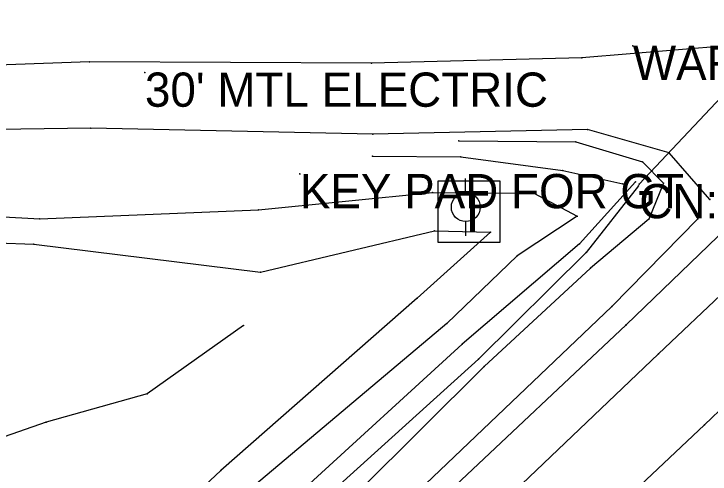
# Model space of a CAD drawing. Extents: x 1419505 to 1434054, y 1956910 to 1968644.
# Drawn here: x 1432529.3 to 1432631, y 1967186.4 to 1967253.6 of the extents above; entities that cross this region are included whole.
import ezdxf

# ---------------------------------------------------------------- set-up
doc = ezdxf.new("R2010")
doc.units = 0
for name, color, linetype in [('S_BREAKLINE', 7, 'Continuous'), ('S_DITCHLINE', 7, 'Continuous'), ('S_DRG_PT_SYM', 7, 'Continuous'), ('S_EDGE_PAVEMENT', 7, 'Continuous'), ('S_GATE_ANNOT', 7, 'Continuous'), ('S_GRAVEL_ROAD', 7, 'Continuous'), ('S_GRD_PT_SYM', 7, 'Continuous'), ('S_MISC_STRUCTURES_ANNOT', 7, 'Continuous'), ('S_MSC_PT_SYM', 7, 'Continuous'), ('S_PAVEMENT_CROWN', 7, 'Continuous'), ('S_RDW_PT_SYM', 7, 'Continuous'), ('S_SHOULDER', 7, 'Continuous'), ('S_SIDE_DRAIN', 7, 'Continuous'), ('S_SIDE_DRAIN_ANNOT', 7, 'Continuous'), ('S_SURVEY_TEXT_ANNOT', 7, 'Continuous'), ('S_TELEPHONE_UTILITIES', 7, 'Continuous')]:
    doc.layers.add(name, color=color, linetype=linetype)

msp = doc.modelspace()

# ---------------------------------------------------------------- linework, layer by layer
at = {"layer": 'S_BREAKLINE'}
for p, q in [((1432594.3055, 1967235.0941), (1432611.3766, 1967234.9541)), ((1432611.3766, 1967234.9541), (1432621.0802, 1967232.0329)), ((1432621.0802, 1967232.0329), (1432624.1824, 1967228.9217)), ((1432624.1824, 1967228.9217), (1432622.0503, 1967223.6513)), ((1432565.0346, 1967224.9874), (1432590.4573, 1967227.5466)), ((1432590.4573, 1967227.5466), (1432605.2522, 1967227.4596)), ((1432605.2522, 1967227.4596), (1432611.5856, 1967224.0844)), ((1432489.0497, 1967226.2985), (1432533.0896, 1967223.6753)), ((1432533.0896, 1967223.6753), (1432565.0346, 1967224.9874)), ((1432611.5856, 1967224.0844), (1432602.8181, 1967218.263)), ((1432622.0503, 1967223.6513), (1432613.4947, 1967216.4619)), ((1432629.1668, 1967223.6783), (1432616.6269, 1967210.8735)), ((1432565.3046, 1967215.9048), (1432590.7483, 1967221.9152)), ((1432598.9288, 1967221.7462), (1432588.1901, 1967212.1096)), ((1432590.7483, 1967221.9152), (1432598.9288, 1967221.7462)), ((1432489.4507, 1967221.5802), (1432532.2115, 1967219.9741)), ((1432532.2115, 1967219.9741), (1432565.3046, 1967215.9048)), ((1432602.8181, 1967218.263), (1432592.5354, 1967208.3994)), ((1432613.4947, 1967216.4619), (1432597.9657, 1967202.1109)), ((1432588.1901, 1967212.1096), (1432559.5073, 1967186.919)), ((1432616.6269, 1967210.8735), (1432570.1649, 1967166.6427)), ((1432562.8275, 1967208.1103), (1432548.7766, 1967198.1167)), ((1432592.5354, 1967208.3994), (1432562.6185, 1967183.2037)), ((1432597.9657, 1967202.1109), (1432571.475, 1967175.7472)), ((1432548.7766, 1967198.1167), (1432534.0146, 1967193.9934)), ((1432534.0146, 1967193.9934), (1432520.4247, 1967189.2581)), ((1432559.5073, 1967186.919), (1432543.0472, 1967171.614))]:
    msp.add_line(p, q, dxfattribs=at)
at = {"layer": 'S_DITCHLINE'}
for p, q in [((1432581.6877, 1967232.8479), (1432594.5755, 1967232.7279)), ((1432594.5755, 1967232.7279), (1432609.4605, 1967230.7678)), ((1432609.4605, 1967230.7678), (1432618.2151, 1967228.7927)), ((1432620.0602, 1967229.1027), (1432611.9246, 1967220.0431)), ((1432620.5392, 1967228.5157), (1432612.8927, 1967218.749)), ((1432611.9246, 1967220.0431), (1432594.7625, 1967205.3892)), ((1432612.8927, 1967218.749), (1432597.1437, 1967203.177)), ((1432594.7625, 1967205.3892), (1432566.7357, 1967179.7665)), ((1432597.1437, 1967203.177), (1432569.0119, 1967177.7844))]:
    msp.add_line(p, q, dxfattribs=at)
at = {"layer": 'S_DRG_PT_SYM'}
msp.add_lwpolyline([(1432620.6352, 1967228.7737), (1432620.6352, 1967228.8237), (1432620.6352, 1967228.7737), (1432620.5852, 1967228.7737), (1432620.6352, 1967228.7737), (1432620.6352, 1967228.7237), (1432620.6352, 1967228.7737), (1432620.6852, 1967228.7737)], dxfattribs=at)
at = {"layer": 'S_EDGE_PAVEMENT'}
for p, q in [((1432647.846, 1967227.1466), (1432623.4514, 1967203.9651)), ((1432623.4514, 1967203.9651), (1432576.4614, 1967159.2652))]:
    msp.add_line(p, q, dxfattribs=at)
at = {"layer": 'S_GRAVEL_ROAD'}
for p, q in [((1432540.563, 1967236.9162), (1432499.9084, 1967236.4522)), ((1432581.7447, 1967236.0441), (1432540.563, 1967236.9162)), ((1432613.0747, 1967236.7212), (1432581.7447, 1967236.0441)), ((1432625.0105, 1967233.325), (1432613.0747, 1967236.7212)), ((1432630.9139, 1967226.5365), (1432625.0105, 1967233.325))]:
    msp.add_line(p, q, dxfattribs=at)
at = {"layer": 'S_GRD_PT_SYM'}
for points in [[(1432594.3055, 1967235.0941), (1432594.3055, 1967235.1441), (1432594.3055, 1967235.0941), (1432594.2555, 1967235.0941), (1432594.3055, 1967235.0941), (1432594.3055, 1967235.0441), (1432594.3055, 1967235.0941), (1432594.3555, 1967235.0941)], [(1432611.3766, 1967234.9541), (1432611.3766, 1967235.0041), (1432611.3766, 1967234.9541), (1432611.3266, 1967234.9541), (1432611.3766, 1967234.9541), (1432611.3766, 1967234.9041), (1432611.3766, 1967234.9541), (1432611.4266, 1967234.9541)], [(1432581.6877, 1967232.8479), (1432581.6877, 1967232.8979), (1432581.6877, 1967232.8479), (1432581.6377, 1967232.8479), (1432581.6877, 1967232.8479), (1432581.6877, 1967232.7979), (1432581.6877, 1967232.8479), (1432581.7377, 1967232.8479)], [(1432594.5755, 1967232.7279), (1432594.5755, 1967232.7779), (1432594.5755, 1967232.7279), (1432594.5255, 1967232.7279), (1432594.5755, 1967232.7279), (1432594.5755, 1967232.6779), (1432594.5755, 1967232.7279), (1432594.6255, 1967232.7279)], [(1432621.0802, 1967232.0329), (1432621.0802, 1967232.0829), (1432621.0802, 1967232.0329), (1432621.0302, 1967232.0329), (1432621.0802, 1967232.0329), (1432621.0802, 1967231.9829), (1432621.0802, 1967232.0329), (1432621.1302, 1967232.0329)], [(1432609.4605, 1967230.7678), (1432609.4605, 1967230.8178), (1432609.4605, 1967230.7678), (1432609.4105, 1967230.7678), (1432609.4605, 1967230.7678), (1432609.4605, 1967230.7178), (1432609.4605, 1967230.7678), (1432609.5105, 1967230.7678)], [(1432618.2151, 1967228.7927), (1432618.2151, 1967228.8427), (1432618.2151, 1967228.7927), (1432618.1651, 1967228.7927), (1432618.2151, 1967228.7927), (1432618.2151, 1967228.7427), (1432618.2151, 1967228.7927), (1432618.2651, 1967228.7927)], [(1432620.0602, 1967229.1027), (1432620.0602, 1967229.1527), (1432620.0602, 1967229.1027), (1432620.0102, 1967229.1027), (1432620.0602, 1967229.1027), (1432620.0602, 1967229.0527), (1432620.0602, 1967229.1027), (1432620.1102, 1967229.1027)], [(1432624.1824, 1967228.9217), (1432624.1824, 1967228.9717), (1432624.1824, 1967228.9217), (1432624.1324, 1967228.9217), (1432624.1824, 1967228.9217), (1432624.1824, 1967228.8717), (1432624.1824, 1967228.9217), (1432624.2324, 1967228.9217)], [(1432620.5392, 1967228.5157), (1432620.5392, 1967228.5657), (1432620.5392, 1967228.5157), (1432620.4892, 1967228.5157), (1432620.5392, 1967228.5157), (1432620.5392, 1967228.4657), (1432620.5392, 1967228.5157), (1432620.5892, 1967228.5157)], [(1432590.4573, 1967227.5466), (1432590.4573, 1967227.5966), (1432590.4573, 1967227.5466), (1432590.4073, 1967227.5466), (1432590.4573, 1967227.5466), (1432590.4573, 1967227.4966), (1432590.4573, 1967227.5466), (1432590.5073, 1967227.5466)], [(1432605.2522, 1967227.4596), (1432605.2522, 1967227.5096), (1432605.2522, 1967227.4596), (1432605.2022, 1967227.4596), (1432605.2522, 1967227.4596), (1432605.2522, 1967227.4096), (1432605.2522, 1967227.4596), (1432605.3022, 1967227.4596)], [(1432565.0346, 1967224.9874), (1432565.0346, 1967225.0374), (1432565.0346, 1967224.9874), (1432564.9846, 1967224.9874), (1432565.0346, 1967224.9874), (1432565.0346, 1967224.9374), (1432565.0346, 1967224.9874), (1432565.0846, 1967224.9874)], [(1432533.0896, 1967223.6753), (1432533.0896, 1967223.7253), (1432533.0896, 1967223.6753), (1432533.0396, 1967223.6753), (1432533.0896, 1967223.6753), (1432533.0896, 1967223.6253), (1432533.0896, 1967223.6753), (1432533.1396, 1967223.6753)], [(1432611.5856, 1967224.0844), (1432611.5856, 1967224.1344), (1432611.5856, 1967224.0844), (1432611.5356, 1967224.0844), (1432611.5856, 1967224.0844), (1432611.5856, 1967224.0344), (1432611.5856, 1967224.0844), (1432611.6356, 1967224.0844)], [(1432629.1668, 1967223.6783), (1432629.1668, 1967223.7283), (1432629.1668, 1967223.6783), (1432629.1168, 1967223.6783), (1432629.1668, 1967223.6783), (1432629.1668, 1967223.6283), (1432629.1668, 1967223.6783), (1432629.2168, 1967223.6783)], [(1432622.0503, 1967223.6513), (1432622.0503, 1967223.7013), (1432622.0503, 1967223.6513), (1432622.0003, 1967223.6513), (1432622.0503, 1967223.6513), (1432622.0503, 1967223.6013), (1432622.0503, 1967223.6513), (1432622.1003, 1967223.6513)], [(1432590.7483, 1967221.9152), (1432590.7483, 1967221.9652), (1432590.7483, 1967221.9152), (1432590.6983, 1967221.9152), (1432590.7483, 1967221.9152), (1432590.7483, 1967221.8652), (1432590.7483, 1967221.9152), (1432590.7983, 1967221.9152)], [(1432598.9288, 1967221.7462), (1432598.9288, 1967221.7962), (1432598.9288, 1967221.7462), (1432598.8788, 1967221.7462), (1432598.9288, 1967221.7462), (1432598.9288, 1967221.6962), (1432598.9288, 1967221.7462), (1432598.9788, 1967221.7462)], [(1432532.2115, 1967219.9741), (1432532.2115, 1967220.0241), (1432532.2115, 1967219.9741), (1432532.1615, 1967219.9741), (1432532.2115, 1967219.9741), (1432532.2115, 1967219.9241), (1432532.2115, 1967219.9741), (1432532.2615, 1967219.9741)], [(1432611.9246, 1967220.0431), (1432611.9246, 1967220.0931), (1432611.9246, 1967220.0431), (1432611.8746, 1967220.0431), (1432611.9246, 1967220.0431), (1432611.9246, 1967219.9931), (1432611.9246, 1967220.0431), (1432611.9746, 1967220.0431)], [(1432612.8927, 1967218.749), (1432612.8927, 1967218.799), (1432612.8927, 1967218.749), (1432612.8427, 1967218.749), (1432612.8927, 1967218.749), (1432612.8927, 1967218.699), (1432612.8927, 1967218.749), (1432612.9427, 1967218.749)], [(1432602.8181, 1967218.263), (1432602.8181, 1967218.313), (1432602.8181, 1967218.263), (1432602.7681, 1967218.263), (1432602.8181, 1967218.263), (1432602.8181, 1967218.213), (1432602.8181, 1967218.263), (1432602.8681, 1967218.263)], [(1432565.3046, 1967215.9048), (1432565.3046, 1967215.9548), (1432565.3046, 1967215.9048), (1432565.2546, 1967215.9048), (1432565.3046, 1967215.9048), (1432565.3046, 1967215.8548), (1432565.3046, 1967215.9048), (1432565.3546, 1967215.9048)], [(1432613.4947, 1967216.4619), (1432613.4947, 1967216.5119), (1432613.4947, 1967216.4619), (1432613.4447, 1967216.4619), (1432613.4947, 1967216.4619), (1432613.4947, 1967216.4119), (1432613.4947, 1967216.4619), (1432613.5447, 1967216.4619)], [(1432588.1901, 1967212.1096), (1432588.1901, 1967212.1596), (1432588.1901, 1967212.1096), (1432588.1401, 1967212.1096), (1432588.1901, 1967212.1096), (1432588.1901, 1967212.0596), (1432588.1901, 1967212.1096), (1432588.2401, 1967212.1096)], [(1432616.6269, 1967210.8735), (1432616.6269, 1967210.9235), (1432616.6269, 1967210.8735), (1432616.5769, 1967210.8735), (1432616.6269, 1967210.8735), (1432616.6269, 1967210.8235), (1432616.6269, 1967210.8735), (1432616.6769, 1967210.8735)], [(1432562.8275, 1967208.1103), (1432562.8275, 1967208.1603), (1432562.8275, 1967208.1103), (1432562.7775, 1967208.1103), (1432562.8275, 1967208.1103), (1432562.8275, 1967208.0603), (1432562.8275, 1967208.1103), (1432562.8775, 1967208.1103)], [(1432592.5354, 1967208.3994), (1432592.5354, 1967208.4494), (1432592.5354, 1967208.3994), (1432592.4854, 1967208.3994), (1432592.5354, 1967208.3994), (1432592.5354, 1967208.3494), (1432592.5354, 1967208.3994), (1432592.5854, 1967208.3994)], [(1432594.7625, 1967205.3892), (1432594.7625, 1967205.4392), (1432594.7625, 1967205.3892), (1432594.7125, 1967205.3892), (1432594.7625, 1967205.3892), (1432594.7625, 1967205.3392), (1432594.7625, 1967205.3892), (1432594.8125, 1967205.3892)], [(1432597.1437, 1967203.177), (1432597.1437, 1967203.227), (1432597.1437, 1967203.177), (1432597.0937, 1967203.177), (1432597.1437, 1967203.177), (1432597.1437, 1967203.127), (1432597.1437, 1967203.177), (1432597.1937, 1967203.177)], [(1432597.9657, 1967202.1109), (1432597.9657, 1967202.1609), (1432597.9657, 1967202.1109), (1432597.9157, 1967202.1109), (1432597.9657, 1967202.1109), (1432597.9657, 1967202.0609), (1432597.9657, 1967202.1109), (1432598.0157, 1967202.1109)], [(1432548.7766, 1967198.1167), (1432548.7766, 1967198.1667), (1432548.7766, 1967198.1167), (1432548.7266, 1967198.1167), (1432548.7766, 1967198.1167), (1432548.7766, 1967198.0667), (1432548.7766, 1967198.1167), (1432548.8266, 1967198.1167)], [(1432534.0146, 1967193.9934), (1432534.0146, 1967194.0434), (1432534.0146, 1967193.9934), (1432533.9646, 1967193.9934), (1432534.0146, 1967193.9934), (1432534.0146, 1967193.9434), (1432534.0146, 1967193.9934), (1432534.0646, 1967193.9934)], [(1432559.5073, 1967186.919), (1432559.5073, 1967186.969), (1432559.5073, 1967186.919), (1432559.4573, 1967186.919), (1432559.5073, 1967186.919), (1432559.5073, 1967186.869), (1432559.5073, 1967186.919), (1432559.5573, 1967186.919)]]:
    msp.add_lwpolyline(points, dxfattribs=at)
at = {"layer": 'S_MSC_PT_SYM'}
for points in [[(1432619.7001, 1967248.964), (1432619.7001, 1967249.014), (1432619.7001, 1967248.964), (1432619.6501, 1967248.964), (1432619.7001, 1967248.964), (1432619.7001, 1967248.914), (1432619.7001, 1967248.964), (1432619.7501, 1967248.964)], [(1432548.4425, 1967245.0607), (1432548.4425, 1967245.1107), (1432548.4425, 1967245.0607), (1432548.3925, 1967245.0607), (1432548.4425, 1967245.0607), (1432548.4425, 1967245.0107), (1432548.4425, 1967245.0607), (1432548.4925, 1967245.0607)], [(1432571.06, 1967230.2388), (1432571.06, 1967230.2888), (1432571.06, 1967230.2388), (1432571.01, 1967230.2388), (1432571.06, 1967230.2388), (1432571.06, 1967230.1888), (1432571.06, 1967230.2388), (1432571.11, 1967230.2388)]]:
    msp.add_lwpolyline(points, dxfattribs=at)
at = {"layer": 'S_PAVEMENT_CROWN'}
for p, q in [((1432639.8124, 1967249.491), (1432612.2587, 1967247.2059)), ((1432612.2587, 1967247.2059), (1432581.5267, 1967246.4168)), ((1432540.352, 1967246.6358), (1432499.3144, 1967245.0467)), ((1432581.5267, 1967246.4168), (1432540.352, 1967246.6358)), ((1432656.4325, 1967218.923), (1432630.1618, 1967193.5964)), ((1432630.1618, 1967193.5964), (1432584.6329, 1967150.7456))]:
    msp.add_line(p, q, dxfattribs=at)
at = {"layer": 'S_RDW_PT_SYM'}
for points in [[(1432612.2587, 1967247.2059), (1432612.2587, 1967247.2559), (1432612.2587, 1967247.2059), (1432612.2087, 1967247.2059), (1432612.2587, 1967247.2059), (1432612.2587, 1967247.1559), (1432612.2587, 1967247.2059), (1432612.3087, 1967247.2059)], [(1432540.352, 1967246.6358), (1432540.352, 1967246.6858), (1432540.352, 1967246.6358), (1432540.302, 1967246.6358), (1432540.352, 1967246.6358), (1432540.352, 1967246.5858), (1432540.352, 1967246.6358), (1432540.402, 1967246.6358)], [(1432581.5267, 1967246.4168), (1432581.5267, 1967246.4668), (1432581.5267, 1967246.4168), (1432581.4767, 1967246.4168), (1432581.5267, 1967246.4168), (1432581.5267, 1967246.3668), (1432581.5267, 1967246.4168), (1432581.5767, 1967246.4168)], [(1432540.563, 1967236.9162), (1432540.563, 1967236.9662), (1432540.563, 1967236.9162), (1432540.513, 1967236.9162), (1432540.563, 1967236.9162), (1432540.563, 1967236.8662), (1432540.563, 1967236.9162), (1432540.613, 1967236.9162)], [(1432581.7447, 1967236.0441), (1432581.7447, 1967236.0941), (1432581.7447, 1967236.0441), (1432581.6947, 1967236.0441), (1432581.7447, 1967236.0441), (1432581.7447, 1967235.9941), (1432581.7447, 1967236.0441), (1432581.7947, 1967236.0441)], [(1432613.0747, 1967236.7212), (1432613.0747, 1967236.7712), (1432613.0747, 1967236.7212), (1432613.0247, 1967236.7212), (1432613.0747, 1967236.7212), (1432613.0747, 1967236.6712), (1432613.0747, 1967236.7212), (1432613.1247, 1967236.7212)], [(1432625.0105, 1967233.325), (1432625.0105, 1967233.375), (1432625.0105, 1967233.325), (1432624.9605, 1967233.325), (1432625.0105, 1967233.325), (1432625.0105, 1967233.275), (1432625.0105, 1967233.325), (1432625.0605, 1967233.325)], [(1432630.9139, 1967226.5365), (1432630.9139, 1967226.5865), (1432630.9139, 1967226.5365), (1432630.8639, 1967226.5365), (1432630.9139, 1967226.5365), (1432630.9139, 1967226.4865), (1432630.9139, 1967226.5365), (1432630.9639, 1967226.5365)], [(1432618.7421, 1967208.2263), (1432618.7421, 1967208.2763), (1432618.7421, 1967208.2263), (1432618.6921, 1967208.2263), (1432618.7421, 1967208.2263), (1432618.7421, 1967208.1763), (1432618.7421, 1967208.2263), (1432618.7921, 1967208.2263)], [(1432623.4514, 1967203.9651), (1432623.4514, 1967204.0151), (1432623.4514, 1967203.9651), (1432623.4014, 1967203.9651), (1432623.4514, 1967203.9651), (1432623.4514, 1967203.9151), (1432623.4514, 1967203.9651), (1432623.5014, 1967203.9651)], [(1432630.1618, 1967193.5964), (1432630.1618, 1967193.6464), (1432630.1618, 1967193.5964), (1432630.1118, 1967193.5964), (1432630.1618, 1967193.5964), (1432630.1618, 1967193.5464), (1432630.1618, 1967193.5964), (1432630.2118, 1967193.5964)]]:
    msp.add_lwpolyline(points, dxfattribs=at)
at = {"layer": 'S_SHOULDER'}
for p, q in [((1432633.559, 1967222.5133), (1432618.7421, 1967208.2263)), ((1432618.7421, 1967208.2263), (1432572.5401, 1967164.7465))]:
    msp.add_line(p, q, dxfattribs=at)
at = {"layer": 'S_SIDE_DRAIN'}
msp.add_line((1432655.2104, 1967265.593), (1432620.6352, 1967228.7737), dxfattribs=at)
at = {"layer": 'S_TELEPHONE_UTILITIES'}
for p, q in [((1432595.2712, 1967227.4706), (1432595.2712, 1967229.598)), ((1432595.2712, 1967223.2507), (1432595.2712, 1967221.1931))]:
    msp.add_line(p, q, dxfattribs=at)
msp.add_lwpolyline([(1432591.2726, 1967220.2384), (1432591.2726, 1967229.2384), (1432600.2726, 1967229.2384), (1432600.2726, 1967220.2384)], close=True, dxfattribs=at)
msp.add_circle((1432595.2926, 1967225.3914), 2.1062, dxfattribs=at)

# ---------------------------------------------------------------- texts
at = {"layer": 'S_GATE_ANNOT'}
msp.add_text("30' MTL ELECTRIC", height=5, dxfattribs=at).set_placement((1432548.4425, 1967240.0607))
at = {"layer": 'S_MISC_STRUCTURES_ANNOT'}
msp.add_text('KEY PAD FOR GT', height=5, dxfattribs=at).set_placement((1432571.06, 1967225.2388))
at = {"layer": 'S_SIDE_DRAIN_ANNOT'}
msp.add_text('CN:10', height=5, dxfattribs=at).set_placement((1432620.6352, 1967223.7737))
at = {"layer": 'S_SURVEY_TEXT_ANNOT'}
msp.add_text('WARD HARRIS LN', height=5, dxfattribs=at).set_placement((1432619.7001, 1967243.964))
at = {"layer": 'S_TELEPHONE_UTILITIES'}
msp.add_text('T', height=6, rotation=360, dxfattribs=at).set_placement((1432593.8358, 1967221.7384))

doc.saveas('drawing.dxf')
